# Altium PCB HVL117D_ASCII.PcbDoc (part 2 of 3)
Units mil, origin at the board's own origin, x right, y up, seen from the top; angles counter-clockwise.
Board outline 2004.03 x 2004.03 mil, 6 copper layers (Top Layer, InternalPlane1, MidLayer1, InternalPlane2, MidLayer2, Bottom Layer), stack 60.56 mil thick; 218 components, 157 nets, 658 pads, 273 vias.
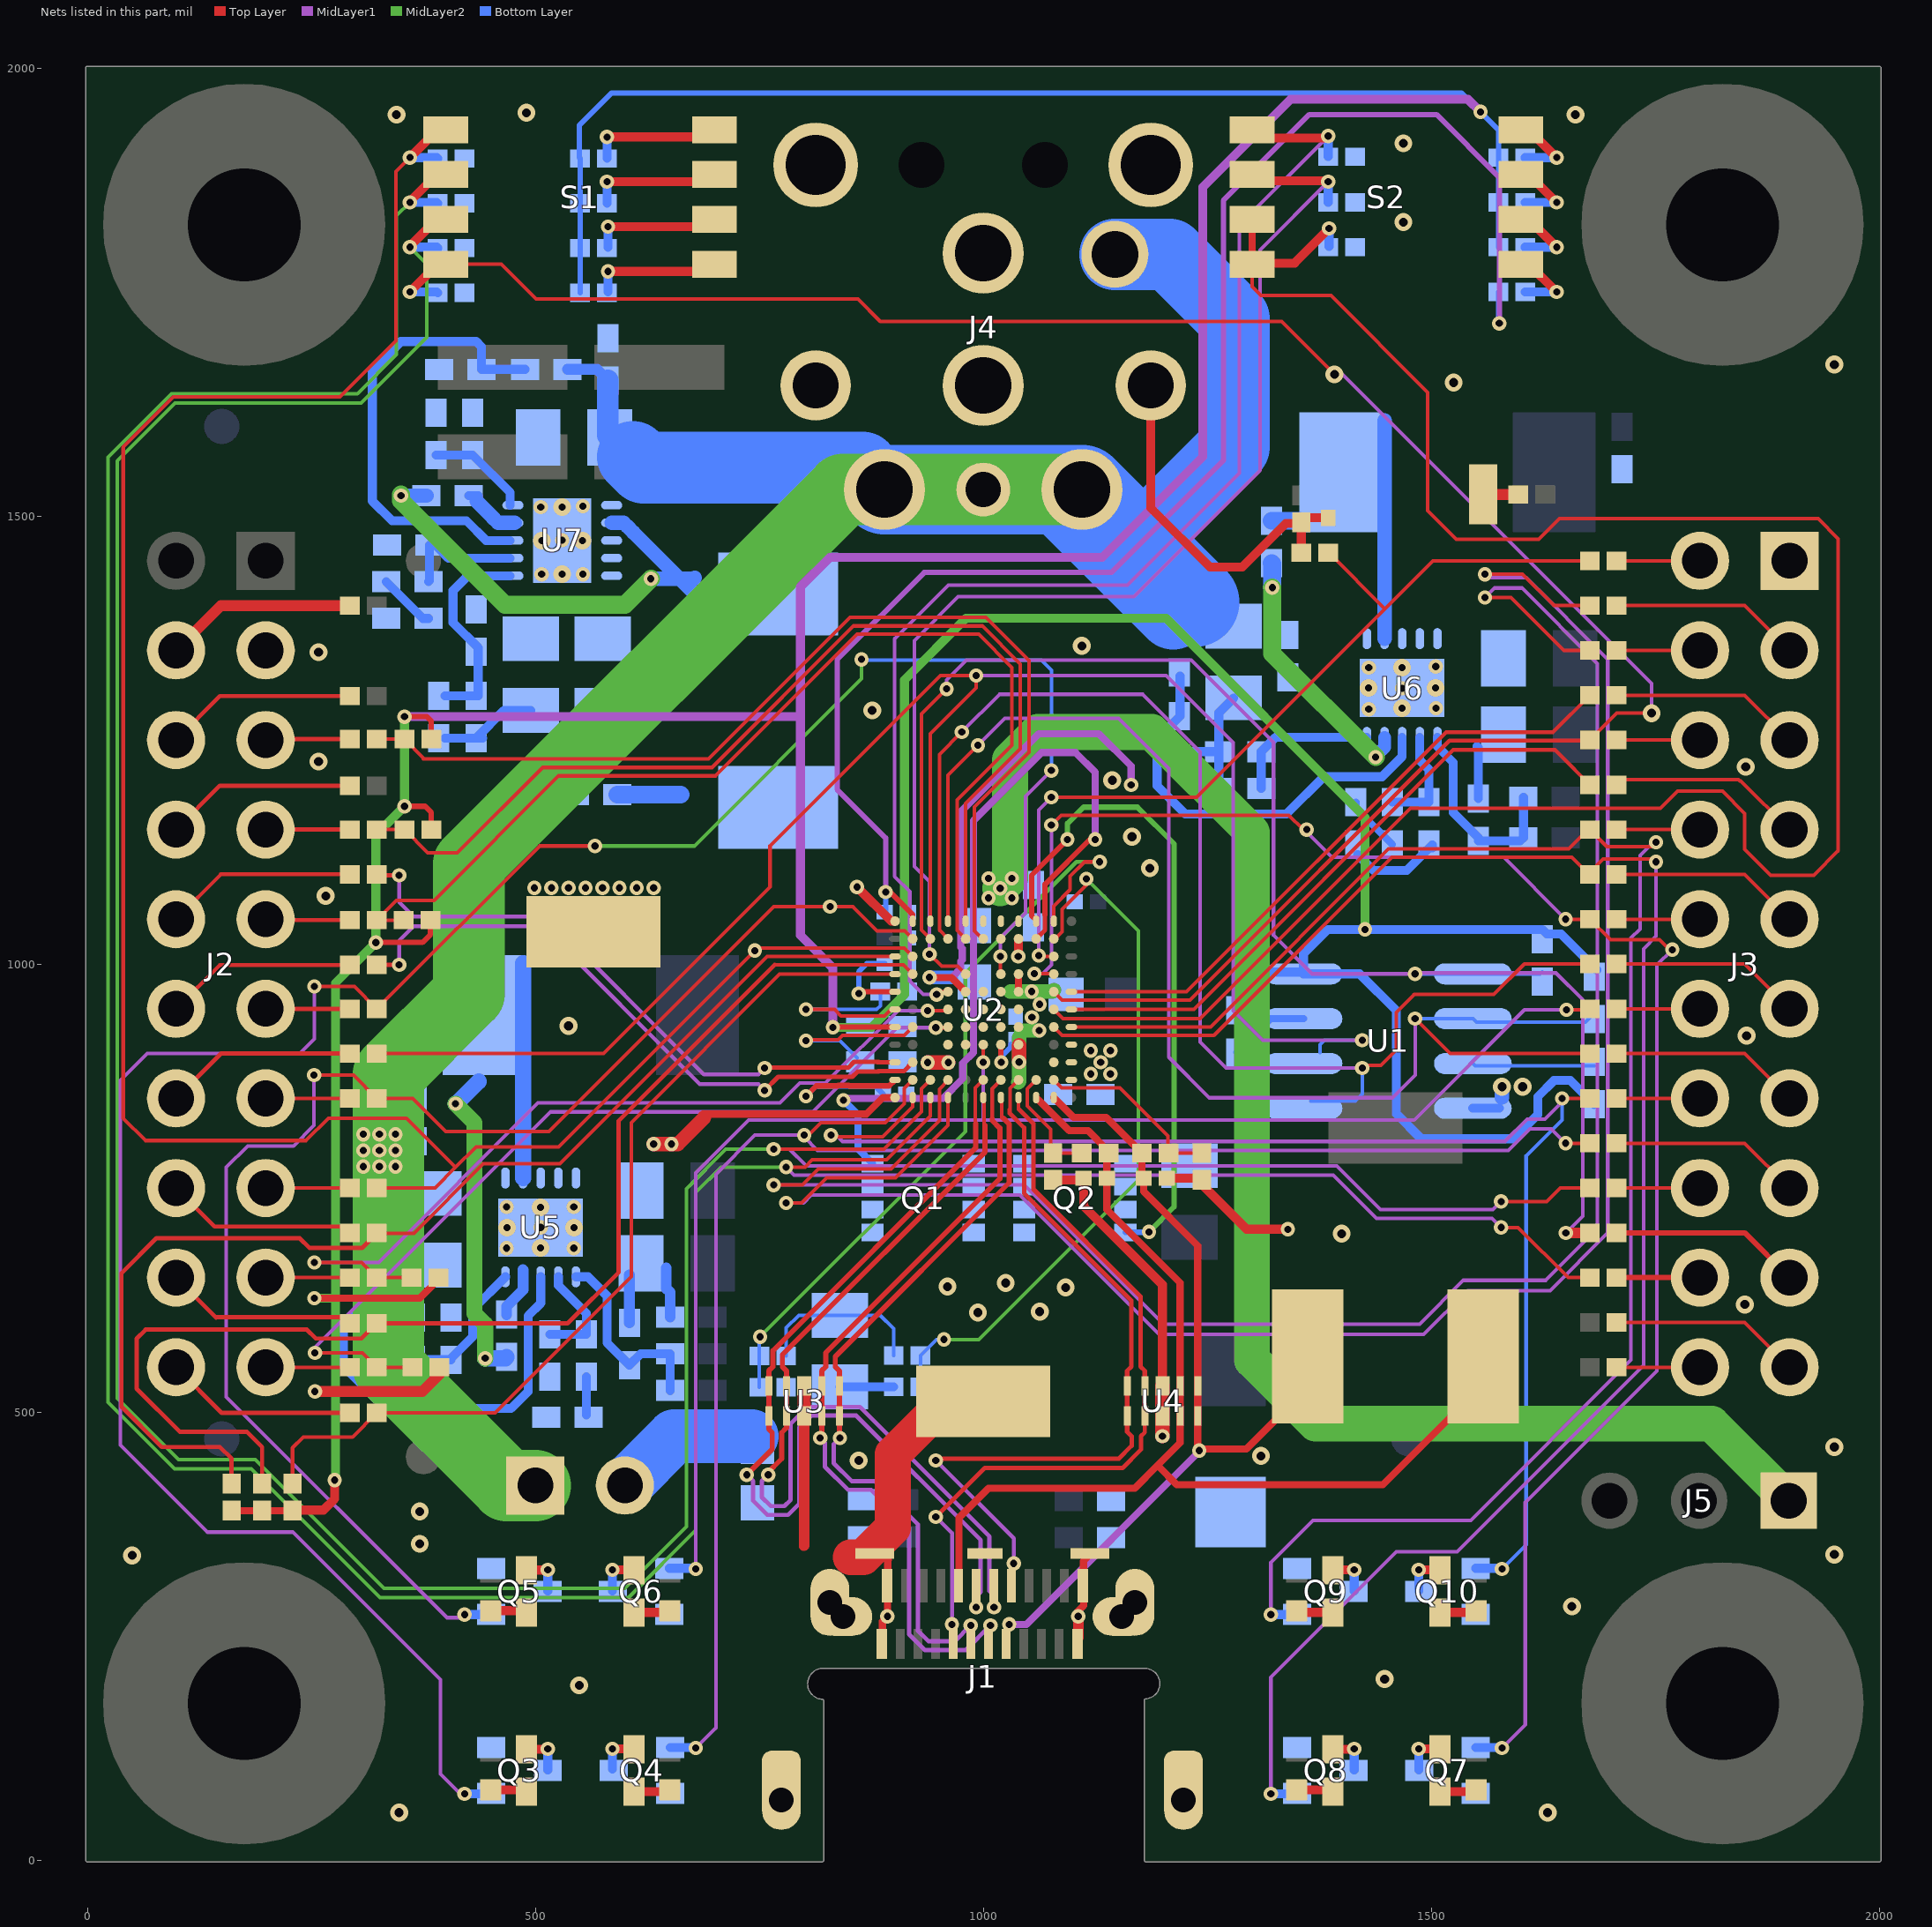
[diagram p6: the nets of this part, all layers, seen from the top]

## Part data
C1 C4: "CAP, CERM, 10 µF, 25 V, +/- 20%, X5R, 0603"
C2 C12: "CAP, CERM, 0.1 µF, 10 V, +/- 10%, X5R, 0201"
C3: "CAP, CERM, 0.22 µF, 6.3 V, +/- 20%, X5R, 0201"
C5: "CAP, CERM, 0.1 µF, 50 V, +/- 20%, C0G/NP0, 0402"
C6: "CAP, CERM, 1 µF, 35 V, +/- 10%, JB, 0402"
C7 C8 C9 C10: "CAP, CERM, 0.01 µF, 50 V, +/- 10%, X7R, 0402"
C11: "CAP, CERM, 22 µF, 10 V, +/- 20%, X5R, 0603"
C13 C16 C17 C18: "CAP, CERM, 1 µF, 10 V, +/- 20%, X5R, 0201"
C14: "CAP, CERM, 10 µF, 10 V, +/- 20%, X5R, 0402"
C15 C19: "CAP, CERM, 220 pF, 25 V, +/- 10%, X7R, 0201"
C20 C23 C26 C31 C34 C37 C42 C45 C48: "CAP, CERM, 0.1uF, 50V, +/-20%, C0G/NP0, 0402"
C22 C33 C44: "CAP, CERM, 10 µF, 25 V, +/- 10%, X5R, 0805"
C24 C25 C35 C36 C46 C47: "CAP, CERM, 22 µF, 35 V, +/- 20%, X5R, 0805"
C27 C30 C38 C41 C49 C52: "CAP, CERM, 120 pF, 50 V, +/- 5%, C0G/NP0, 0402"
C28: "CAP, CERM, 330 pF, 50 V, +/- 5%, C0G/NP0, 0402"
C29: "CAP, CERM, 5600 pF, 50 V, +/- 10%, X7R, 0402"
C39: "CAP, CERM, 100 pF, 50 V, +/- 10%, X7R, 0402"
C40: "CAP, CERM, 2200 pF, 50 V, +/- 10%, X5R, 0402"
C50: "CAP, CERM, 91 pF, 50 V, +/- 5%, C0G/NP0, 0402"
C51: "CAP, CERM, 1800 pF, 50 V, +/- 10%, X7R, 0402"
C53: "CAP, CERM, 0.01 µF, 10 V, +/- 10%, X5R, 0201"
D1: "Diode, Schottky, 40 V, 3 A, SMA"
D2 D3 D4 D5 D6 D7 D8 D9: "LED, White, SMD"
FID1 FID2 FID3 FID4 FID5 FID6: "Fiducial mark.  There is nothing to buy or mount."
H1 H2 H3 H4: "Machine Screw, Round, #4-40 x 1/4, Nylon, Philips panhead"
H5 H6 H7 H8: "Standoff, Hex, 0.5\"L #4-40 Nylon"
J1: "Connector, Receptacle, USB Type C, R/A, SMT"
J2 J3: "Receptacle, 100mil, 10x2, Gold, TH"
J4: "Connector,  DC Power Jack, R/A, 3 Pos, TH"
J5: "Receptacle, 100mil, 3x1, Gold, TH"
J6: "Header, 100mil, 2x1, Tin, TH"
J7: "Header, 100mil, 2x2, Tin, SMT"
L1: "Ferrite Bead, 21 ohm @ 100MHz, 6A, 0805"
Logo1: library part TI_Logo, "Texas Instrument Corporate Signature"
Logo2: library part Pb-Free
Logo3: library part FCC_disclaimer, "FCC_disclaimer"
Q1 Q2: "MOSFET, N-CH, 30 V, 60 A, SON 3.3x3.3mm"
Q3 Q4 Q5 Q6 Q7 Q8 Q9 Q10: library part "DTC114EUAT106, Rohm", "Transistor, NPN, 50 V, 0.05 A, SOT-323"
R1: "RES, 0.01 ohm, 1%, 0.25W, 0805"
R2 R3 R5 R6 R10 R11 R16 R17 R18 R19 R22 R23 R30 R31 R32 R34 R35 R36 R37 R38 R39 R40 R41 R46 R47 R48 R50 R51 R53 R54 R56 R57 R58 R59 R60 R61 R62 R63 R64 R65 R66 R67 R68 R69 R71: "RES, 0, 5%, 0.05 W, 0201"
R4 R7 R8 R9: "RES, 3.3 k, 5%, 0.063 W, 0402"
R12 R13 R14 R15 R27 R42 R43 R44 R45: "RES, 1.00 k, 1%, 0.05 W, 0201"
R20 R75 R76 R79 R80: "RES, 3.83 k, 1%, 0.05 W, 0201"
R21 R24 R25 R26 R29 R33 R49 R52 R55 R70: "RES, 100 k, 1%, 0.05 W, 0201"
R28: "RES, 15.0 k, 1%, 0.063 W, 0402"
R72 R73 R74 R86 R87 R89 R90 R96: "RES, 560, 5%, 0.063 W, 0402"
R77 R78: "RES, 9.09 k, 1%, 0.05 W, 0201"
R81 R91 R101: "RES, 220 k, 5%, 0.063 W, 0402"
R82 R92 R102: "RES, 100 k, 1%, 0.063 W, 0402"
R83 R93 R103: "RES, 43.2 k, 1%, 0.063 W, 0402"
R84: "RES, 32.4 k, 1%, 0.063 W, 0402"
R85: "RES, 2.74 k, 1%, 0.063 W, 0402"
R88 R97 R109: "RES, 47.5 k, 1%, 0.063 W, 0402"
R94: "RES, 19.1 k, 1%, 0.063 W, 0402"
R95: "RES, 8.45 k, 1%, 0.063 W, 0402"
R104: "RES, 7.15 k, 1%, 0.063 W, 0402"
R108: "RES, 9.53 k, 1%, 0.063 W, 0402"
S1 S2: "DIP Switch, SPST 4Pos, Slide, SMT"
S3: "SWITCH TACTILE SPST-NO 0.05A 12V"
TP1 TP2 TP3 TP4 TP5: library part 5019, "Test Point, Miniature, SMT"
U1: "3V, 8Mbit, Serial Flash Memory with Dual and Qual SPI, SOIC-8"
U2: "TPS65982 Preview Specification, ZQZ0096A"
U3 U4: "1, 4, 6 CHANNEL PROTECTION SOLUTION FOR SUPER-SPEED (UP TO 6 GBPS) INTERFACE, DQA0010A"
U5 U6 U7: "4.5V to 28V Input, 3A Output, Synchronous SWIFT Step-Down DC-DC Converter, DRC0010J"
ZZ2 ZZ3 ZZ4: library part AssemblyNote

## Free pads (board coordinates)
  round 75 hole 52: 0(1147,1792)

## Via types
v1: diameter 16, hole 8, Top Layer to Bottom Layer, tented both sides, 166 vias
v2: diameter 16, hole 8.1, Top Layer to Bottom Layer, tented both sides, 54 vias
v3: diameter 20, hole 10, Top Layer to Bottom Layer, tented both sides, 41 vias
v4: diameter 19.68, hole 7.87, Top Layer to Bottom Layer, 12 vias

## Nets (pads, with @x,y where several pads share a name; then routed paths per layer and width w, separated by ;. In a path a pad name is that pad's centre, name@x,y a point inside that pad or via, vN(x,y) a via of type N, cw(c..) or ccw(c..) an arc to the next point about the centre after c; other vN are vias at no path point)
3V3_VSENSE: C27.2 R82.1 R84.2 U5.6 | length 222.7
  Bottom Layer w10: U5.6@545.37,650.88 558.88,650.88 580,629.76 580,577.38 R84.2@605,552.38 617.62,565 647.38,565 R82.1@650.38,565 C27.2@650.38,524
5V_VSENSE: C38.2 R92.1 R94.2 U6.6 | length 231.3
  Bottom Layer w10: U6.6@1506.97,1252.88 1506.97,1242.63 1524.6,1225 1524.6,1169 1552.6,1141 R94.2@1552.6,1137.38 1599.35,1137.38 C38.2@1602.98,1141 R92.1@1602.98,1186
12V_VSENSE: C49.2 R102.1 R104.2 U7.6 | length 236.7
  Bottom Layer w10: C49.2@399.12,1299.31 436.12,1299.31 436.12,1353.06 408.12,1381.06 408.12,1416.69 424.75,1433.32 U7.6@472,1433.32
AUX_N: R34.2 U2.J2 | length 720.6
  Top Layer w5: R34.2@322.96,999 v1(348,999) ; v1(756,859) 771,874 853.85,874 859.66,879.82 883,879.82 ; 883,880.32 911.26,880.32 U2.J2@921.26,890.32
  MidLayer1 w4.4: v1(348,999) 348,1026.1 364,1042.1 507.44,1042.1 683.49,866.05 748.95,866.05 v1(756,859)
AUX_P: R31.2 U2.J1 | length 693.9
  Top Layer w5: R31.2@323.96,1099 v1(348,1099) ; v1(756,884) 756.5,884.5 849.5,884.5 855.82,890.82 883,890.82 ; 882,890.32 U2.J1@901.57,890.32
  MidLayer1 w4.4: v1(348,1099) 348,1069 364,1053 511.95,1053 688,876.95 748.95,876.95 v1(756,884)
BUSPOWERZ: R49.1 S2.3 S2.4 U2.F10 | length 2459.4
  Top Layer w4: U2.F10@1078.74,949.37 1088.94,939.17 1242.17,939.17 1477,1174 1756,1174 1775,1193 1825,1193 1850,1168 1850,1128 1879,1099 1927,1099 1954.33,1126.33 1954.33,1474.67 1932,1497 1643,1497 1620,1474 1528,1474 1496,1506 1496,1638 1388,1746 1310,1746 1300,1756 S2.4@1300,1781
  Top Layer w8: S2.4@1300,1781 S2.3@1300,1831
  Top Layer w10: S2.4@1313,1782 1347,1782 ; 1348,1782 1347,1782 ; v1(1386,1821) 1347,1782
  Bottom Layer w10: R49.1@1386,1800.96 v1(1386,1821)
C_CC1: C15.1 J1.A5 R10.2 TP1.1 U2.L9 U4.2 U4.9 | length 1273.6
  Top Layer w8: J1.A5@973.11,305.31 973,305.42 973,382 1006,415 1169.1,415 1194.55,440.45 ; U2.L9@1061,849 1096,814 1117,814 1138,793 C15.1@1138,761 1138,726 1219.69,644.31 U4.2@1219.69,529.1 U4.9@1219.69,495.64 1219.69,465.58 1194.55,440.45 ; TP1.1@1550.5,569.5 1550.5,523.5 1446,419 1216,419 1194.55,440.45
C_CC2: C19.1 J1.B5 R11.2 TP2.1 U2.L10 U4.1 U4.10 | length 964.3
  Top Layer w8: U2.L10@1078.74,850.94 1100.89,828.8 1137.24,828.8 R11.2@1177.04,789 1177.04,762.97 C19.1@1179.01,761 1179.01,745.99 1239.37,685.63 U4.1@1239.37,529.1 U4.10@1239.37,495.64 v1@1239.37,458.63 ; v1(1241,457) v1@1239.37,458.63 ; 1302.96,468 1293.59,458.63 v1@1239.37,458.63 ; 1303,468 1377,542 TP2.1@1377,562
  MidLayer1 w8: v1(1029,263) 1048,263 v1@1239.37,454.37
C_SBU_N: J1.B8 U2.L8 U4.4 U4.7 | length 840.3
  Top Layer w4: 1039.37,837.63 U2.L8@1039.37,850.94
  Top Layer w4.8: v1(947,383) 1001.6,437.6 1155.6,437.6 1176,458 1176,473 1180.32,477.32 U4.7@1180.32,495.64
  Top Layer w5: 1040.08,837.63 1056,821.71 1056,748.5 1175.72,628.78 1175.72,550.59 1180.32,546 U4.4@1180.32,529.1 U4.7@1180.32,495.64
  MidLayer1 w4.4: v1(947,383) 965,365 v1(965,263)
C_SBU_P: J1.A8 U2.K8 U4.5 U4.6 | length 892.4
  Top Layer w4: 1030,837 1030,861.26 U2.K8@1039.37,870.63
  Top Layer w4.4: J1.A8@1032.17,305.31 1032.3,305.44 1034,307.15 v1(1034,331)
  Top Layer w5: v1(947,446) 949,448 1151.29,448 1165.6,462.31 1165.6,473 1160.63,477.97 U4.6@1160.63,495.64 U4.5@1160.63,529.1 1160.63,546 1165.22,550.59 1165.22,624.43 1045.5,744.15 1045.5,817.36 1029.37,833.49 1029.37,837.63 ; J1.A8@1032.17,305.31 1032.17,306.26 J1.A8@1032.17,321.83
  MidLayer1 w4.4: v1(947,446) 1034,359 v1(1034,331)
C_USB_B_N: J1.B7 U2.L7 U3.1 U3.10 | length 806.4
  Top Layer w4: 1020.68,828.32 U2.L7@1020.68,848.94
  Top Layer w5.8: v1(840,471) 839.37,471.63 U3.10@839.37,495.64 U3.1@839.37,529.1 839.37,546 834.8,550.57 834.8,561.8 1029,756 1029,821.27 1022.27,828
  MidLayer1 w4.8: v1(840,471) 833,464 833,443 853,423 878.86,423 927,374.86 927,256 939,244 968,244 v1(986,262)
C_USB_B_P: J1.B6 U2.K7 U3.2 U3.9 | length 875.1
  Top Layer w4: 1010,828 1010,860.94 U2.K7@1019.68,870.63
  Top Layer w5.8: v1(818,471) 819.69,472.69 U3.9@819.69,495.64 U3.2@819.69,529.1 819.69,546 824.25,550.57 824.25,566.17 1018.45,760.37 1018.45,816.9 1010,825.35 1010,828
  MidLayer1 w4.8: v1(818,471) 823.2,465.8 823.2,438.94 848.94,413.2 874.8,413.2 917.2,370.8 917.2,251.94 934.94,234.2 980.2,234.2 v1(1008,262)
C_USB_T_N: J1.A7 U2.L6 U3.4 U3.7 | length 1057.1
  Top Layer w4: 1001,820 U2.L6@1001,848.94
  Top Layer w5.8: v1@756,429 758.5,431.5 775,448 775,477 780.32,482.32 U3.7@780.32,495.64 U3.4@780.32,529.1 780.32,546 775.75,550.57 775.75,564 1002,790.25 1002,820
  MidLayer1 w4.8: v1(760,430) 752.9,422.9 752.9,405 762.9,395 778,395 785,402 785,486.86 803.94,505.8 862.2,505.8 1006.9,361.1 1006.9,300.1 1012,295 v1(1012,282) 1011,281 1011,278 1012.75,279.75 v1@1012.75,281.5
C_USB_T_P: J1.A6 U2.K6 U3.5 U3.6 | length 1076.2
  Top Layer w4: 991,822 991,861.63 U2.K6@1000,870.63
  Top Layer w5.8: v1(736,430) 764.45,458.45 764.45,477 760.63,480.82 U3.6@760.63,495.64 U3.5@760.63,529.1 760.63,546 765.2,550.57 765.2,568.37 991.45,794.62 991.45,822
  MidLayer1 w4.8: v1(736,430) 743.1,422.9 743.1,400.94 758.84,385.2 782.06,385.2 794.8,397.94 794.8,482.8 808,496 858.14,496 997.1,357.04 997.1,299.1 992,294 v1(992,282)
DEBUG_1: Q10.1 R61.1 U2.L2 | length 1570.6
  Top Layer w4: v1@829,813.37 835.37,807 887.63,807 921.26,840.63 U2.L2@921.26,850.94 ; v1@1650,850 R61.1@1677.04,850
  MidLayer1 w4: v1(830,809) 836,809 843,802 1582,802 1607,827 1627,827 v1@1650,850
  Bottom Layer w4: v1(1579,325) 1606,352 1606,786 1646,826 v1(1646,850)
  Bottom Layer w10: Q10.1@1549.5,325.59 v1@1578.41,325.59
DEBUG_2: Q4.1 R64.1 U2.K2 | length 1847.9
  Top Layer w4: v1@805,809 819,823 890.63,823 911.91,844.28 911.91,846.55 912,846.63 912,855.26 911.91,855.34 911.91,861.28 U2.K2@921.26,870.63 ; v1(1650,800) R64.1@1677.04,800
  MidLayer1 w4: v1(679,125) 701.5,147.5 701.5,765.5 745,809 v1(800,809) 800,807 815,792 1586.14,792 1610.14,816 1634,816 v1(1650,800)
  Bottom Layer w10: Q4.1@650.5,125.59 v1@678.41,125.59
DEBUG_3: R29.1 R65.1 S1.2 U2.L3 | length 4097
  Top Layer w4: v1(780,773.37) 801,773.37 809,781.37 892,781.37 940.94,830.32 U2.L3@940.94,850.94 ; v1(1578,706) 1597,706 1653,650 R65.1@1677.04,650
  Top Layer w10: v1(360,1850) 359,1850 S1.2@390,1881
  MidLayer1 w4: v1(780,773.37) 788.87,764.5 1390.5,764.5 1439,716 1568,716 v1(1578,706)
  MidLayer2 w4: v1(360,1850) 345,1835 345,1680 301.37,1636.37 93.7,1636.37 23,1565.67 23,511 97.37,436.63 183.01,436.63 326.64,293 604,293 679,368 679,745 707.37,773.37 v1(780,773.37)
  Bottom Layer w10: v1(360,1850) 390.04,1850 R29.1@391.04,1849
DEBUG_4: R25.1 R63.1 S1.3 U2.K3 | length 4045.7
  Top Layer w4: v1(766,793.37) 889,793.37 931,835.37 931,860.68 U2.K3@940.94,870.63 ; v1(1578,735) 1629,735 1644,750 R63.1@1677.04,750
  Top Layer w10: v1(360,1800) 359,1800 S1.3@388,1829
  MidLayer1 w4: v1(766,793.37) 783.63,793.37 802.5,774.5 1394.64,774.5 1443.14,726 1569,726 v1(1578,735)
  MidLayer2 w4: v1(360,1800) 379,1781 379,1699.33 305.67,1626 98,1626 33.37,1561.37 33.37,515.3 101.67,447 187.3,447 330.93,303.37 599.7,303.37 668.63,372.3 668.63,749.3 712.7,793.37 v1(766,793.37)
  Bottom Layer w10: v1(360,1800) 390.04,1800 R25.1@391.04,1799
DEBUG_CTL1: R55.1 S2.1 U2.E4 | length 1422
  Top Layer w4: v1@948,965 952.06,969.06 U2.E4@960.63,969.06
  Top Layer w10: S2.1@1306,1922 1383,1922 v1(1385,1924)
  MidLayer1 w4: v1@949,966 v1(948,966) 933,966 918,981 918,1080.75 901,1097.75 901,1363 961,1423 1161,1423 1286,1548 1286,1825 v1(1385,1924)
  Bottom Layer w10: v1(1385,1924) R55.1@1385.04,1901 R55.1@1385.04,1901
DEBUG_CTL2: R52.1 S2.2 U2.D5 | length 1334.2
  Top Layer w4: v1(940,1011) 953.5,997.5 971.56,997.5 U2.D5@980.32,988.74
  Top Layer w10: S2.2@1304,1874 1386,1874 v1(1385,1873)
  MidLayer1 w4: v1@940,1008 v1(940,1011) 940,1092 923,1109 923,1361 972,1410 1168,1410 1309,1551 1309,1797 v1(1385,1873)
  Bottom Layer w10: v1(1385,1873) R52.1@1385.04,1850 R52.1@1385.04,1850
"EXTERNAL POWER": C22.1 C23.1 C33.1 C34.1 C44.1 C45.1 J4.1 J4.2 J4.3 J6.1 pad.0 R81.2 R91.2 R101.2 U5.1 U6.1 U7.1 | length 3136.3
  MidLayer2 w80: J6.1@500,418 468,418 336,550 336,877 425.9,966.9 425.9,1111.9 843.53,1529.53 J4.3@889.76,1529.53 J4.1@1000,1529.53 J4.2@1110.24,1529.53
  Bottom Layer w12: R101.2@535.74,1663.69 568.69,1663.69 C45.1@581,1651.38
  Bottom Layer w24: C44.1@581,1589.8 C45.1@581,1651.38
  Bottom Layer w80: 609,1566 621,1554 865.29,1554 J4.3@889.76,1529.53 ; J4.2@1073.47,1529.53 1212,1391 ; pad.0@1147,1792 1208,1792 1280,1720 1280,1577 1171.38,1468.38
  Bottom Layer w100: J4.3@889.76,1529.53 J4.1@1000,1529.53 1073.47,1529.53 J4.2@1110.24,1529.53 1171.38,1468.38 1235.76,1404
  other v1: 308,774 326,774 344,774 308,792 326,792 344,792 308,810 326,810 344,810
GND: C1.2 C2.2 C3.2 C4.2 C5.2 C6.2 C7.2 C8.2 C9.2 C10.2 C11.2 C12.2 C13.2 C14.2 C15.2 C16.2 C17.2 C18.2 C19.2 C22.2 C23.2 C24.2 C25.2 C26.2 C28.2 C29.2 C30.2 C33.2 C34.2 C35.2 C36.2 C37.2 C39.2 C40.2 C41.2 C44.2 C45.2 C46.2 C47.2 C48.2 C50.2 C51.2 C52.2 C53.2 D1.2 J1.1 J1.2 J1.3 J1.A1 J1.A12 J1.B1 J1.B12 J1.H1 J1.H2 J1.H3 J1.H4 J1.H5 J1.H6 J1.H7 J1.H8 J2.3 J3.1 J4.4 J4.5 J4.6 J4.7 J4.8 J4.9 Q3.2 Q4.2 Q5.2 Q6.2 Q7.2 Q8.2 Q9.2 Q10.2 R21.2 R22.2 R24.2 R25.2 R26.1 R28.1 R29.2 R30.2 R33.2 R49.2 R52.2 R55.2 R56.1 R70.1 R83.1 R84.1 R88.1 R93.1 R94.1 R97.1 R103.1 R104.1 R109.1 TP4.1 TP5.1 U1.4 U2.A1 U2.B8 U2.D8 U2.E5 U2.E6 U2.E7 U2.E8 U2.F5 U2.F6 U2.F7 U2.F8 U2.G5 U2.G6 U2.G7 U2.G8 U2.H4 U2.H5 U2.H8 U2.L1 U3.3 U3.8 U4.3 U4.8 U5.3 U5.4 U5.5 U5.11 U6.3 U6.4 U6.5 U6.11 U7.3 U7.4 U7.5 U7.11 | length 3329
  Top Layer w6: R22.2@1077.02,760.47 R22.2@1077.02,761 ; C15.2@1110.06,759.04 C15.2@1112.02,761 ; R30.2@1237.04,761 R30.2@1239,759.04
  Top Layer w8: 687.5,832.5 869.5,832.5 887.94,850.94 U2.L1@901.57,850.94 ; J1.B12@887.48,240.35 887.48,266.48 v1(893,272) 893,304.93 893.39,305.31 893.39,334.39 894,335 ; v2(940,985) 964.37,985 U2.E5@980.32,969.06 ; U2.E8@1039.37,969.06 U2.D8@1039.37,988.74 ; J1.B1@1105.98,240.35 v1(1106,272) 1106,278 1112,284 1112,305.2 1111.89,305.31 1111.89,333.46 J1.1@1119.76,341.34
  Top Layer w10: 799,350 800,351 ; v1(859,1086) 897.2,1047.8 U2.A1@901.57,1047.8 ; v2(1039,1008.37) 1039.37,1008.74 U2.B8@1039.37,1028.11 ; R22.2@1078,759.04 C15.2@1110.06,759.04 ; C15.2@1112.02,761 1112.02,729.98 1200,642 U4.8@1200,495.64 ; J4.6@1187.01,1645.67 1187.01,1508.99 1253,1443 1289,1443 1337.68,1491.68 1353.64,1491.68 R26.1@1355,1493.04 1359.97,1498.01 C53.2@1385,1498.01 ; C19.2@1204.99,761 R30.2@1237.04,761 ; R30.2@1239,759.04 1294.04,704 v1(1340,704) ; R70.1@1355.04,1459 R26.1@1355,1493.04
  Top Layer w12: v1(254,523) 374,523 392.96,541.96 R24.2@392.96,550 ; 800,351 U3.8@800,495.64 ; v1(1106,272) 1106.3,271.7 J1.B1@1106.3,248.3
  Top Layer w15: U3.8@800,495.64 U3.3@800,529.1
  Top Layer w16: v1(632,799) v1(652,799) 659,799 688.5,828.5 ; v2(938,890) v2(961,890) ; v2(1040,890.67) U2.H8@1040,909.37 ; v1(1200,473) U4.8@1200,495.64 U4.3@1200,529.1
  Top Layer w40: 852,338 866,338 899,371 899,453 958,512 TP4.1@1000,512
  MidLayer1 w8: v2(940,985) 965,985 975,995 975,1003.08 976.5,1004.58 976.5,1017.42 975,1018.92 975,1170 1062,1257 1129,1257 1165,1221 v2(1165,1200)
  MidLayer2 w16: 1030,969 1030.37,969.37 v2(1054,969.37) 1077.37,969.37 1079,971 ; 1039,868 1040,869 v2(1040,890.67) 1040,918 ; 1042.33,925.67 v2(1062.3,925.67)
  Bottom Layer w8: C40.2@1416,1180.62 1416,1173.98 C39.2@1456.6,1133.38
  Bottom Layer w10: R93.1@1219.6,1229.38 1227.22,1237 C41.2@1262.98,1237 ; R97.1@1262.98,1196 C41.2@1262.98,1237 ; C33.2@1279.6,1297 1262.98,1280.38 C41.2@1262.98,1237 ; U1.4@1546.49,839 U1.4@1576,839 ; 1551,1243 1552.6,1241.4 R94.1@1552.6,1184.62
  Bottom Layer w12: R84.1@605,599.62 C25.2@605,653 ; 646.1,660.8 646.1,637.96 650.38,633.68 C26.2@650.38,606
  Bottom Layer w15: v2(940,985) 964.37,985
  Bottom Layer w16: 1579,851 v3(1579,863)
  other v2: 468,683 543,683 506,706 468,729 543,729 1054.3,940.57 1062.8,955.07 499,1085 518,1085 537,1085 556,1085 575,1085 594,1085 613,1085 632,1085 1430.2,1284.4 1505.3,1285.5 1467.6,1307.67 1430.2,1330.7 1505,1332.1 507,1435 553,1435 530,1473 506,1510 553,1511
  other v3: 348,53 1630,53 549,195 1448,202 1657,283 50,340 1950,341 371,353 371,389 861,446 1310,451 1950,461 994,611 1063,612 1850,620 1092,639 960,640 1025,644 1400,699 1602,863 1852,920 537,931 266,1076 1186,1107 1166,1142 1144,1205 1851,1220 258,1226 876,1283 258,1348 1110,1355 1525,1649 1950,1669 1469,1828 1469,1916 345,1948 1661,1948 490,1950
  other v4: 506,683.36 468.6,706 543.4,706 506,728.64 1467.6,1285.36 1430.2,1308 1505,1308 1467.6,1330.64 530.12,1435.28 507.48,1472.69 552.76,1472.69 530.12,1510.09
GPIO0: Q5.1 R35.1 U2.B2 | length 1636.4
  Top Layer w4: v1(253,876) 296.96,876 R35.1@322.96,850 363,850 400,813 515,813 766,1064 v1(829,1064) 854.47,1064 881.47,1037 912.37,1037 U2.B2@921.26,1028.11
  MidLayer1 w4: v1(253,876) 253,820 230,797 179,797 155,773 155,517 401.5,270.5 v1@417.5,270.5
  Bottom Layer w10: v1(421,274) Q5.1@450.09,274
GPIO1: R33.1 R37.1 S1.1 U2.C2 | length 2526.5
  Top Layer w4: R37.1@322.96,750 388,750 411,773 ; v1(360,1900) 344.5,1884.5 344.5,1695.5 282,1633 96,1633 40,1577 40,828 65,803 244,803 269,828 356,828 411,773 ; U2.C2@921.26,1008.43 911.68,1018 748,1018 v1(745,1015) 526,796 434,796 411,773
  Top Layer w10: v1(360,1900) S1.1@398,1938
  Bottom Layer w10: v1(360,1900) 390.04,1900 R33.1@391.04,1899
GPIO2: Q7.1 R57.1 U2.D10 | length 1964.3
  Top Layer w4: v1(1057,989.37) 1078.11,989.37 U2.D10@1078.74,988.74 ; v1@1082,1155 v1(1076,1155) 1087,1166 1341,1166 v1@1357,1150 ; v1(1650,1050) R57.1@1677.04,1050 1700.04,1027 1755,1027 1766,1016 v1(1769,1016)
  MidLayer1 w4: v1(1057,989.37) 1066.46,989.37 1076,998.91 v1(1076,1155) ; v1@1358,1150 1389,1119 1581,1119 v1(1650,1050) ; v1(1579,125) 1605,151 1605,398.99 1752,545.99 1752,999 v1(1769,1016)
  Bottom Layer w10: Q7.1@1549.5,125.59 v1@1578.41,125.59
  other v1: 1361,1150
GPIO3: Q9.1 R53.1 U2.G11 | length 1923
  Top Layer w4: U2.G11@1098.43,929.69 1253.69,929.69 1452.35,1128.35 1653.35,1128.35 R53.1@1673,1148 ; R53.1@1677.04,1150 1696.04,1131 1746,1131 v1(1751,1136)
  MidLayer1 w4: v1(1321,274) 1321,332 1368,379 1544,379 1723,558 1723,1029 1733,1039 1733,1121 1748,1136 v1(1751,1136)
  Bottom Layer w10: v1(1321,274) Q9.1@1350.09,274
GPIO4_HPD: R46.2 R70.2 U2.C10 | length 1002.2
  Top Layer w4: v1(1062,1009.37) 1062.94,1008.43 U2.C10@1078.74,1008.43 ; v1(1076,1186) 1238,1186 1448.46,1396.46 ; R70.2@1384.96,1459 1385.91,1459 1448.46,1396.46 ; R46.2@1677.04,1450 1502,1450 1448.46,1396.46
  MidLayer1 w4: v1(1062,1009.37) 1062,1172 v1(1076,1186) v1@1078,1188
GPIO5_HPD: R21.1 R50.2 S1.4 U2.E10 | length 2455
  Top Layer w4: S1.4@400,1781 462,1781 501,1742 860,1742 885,1717 1333,1717 v3(1392,1658) ; U2.E10@1078.74,969.06 1088.09,959.71 1230.71,959.71 1520.34,1249.34 R50.2@1676.38,1249.34 ; R50.2@1674.69,1247.65 R50.2@1676.38,1249.34 ; R50.2@1677.04,1249.34 R50.2@1676.38,1249.34 ; v3(1746,1280) 1707.04,1280 R50.2@1677.04,1250 R50.2@1676.38,1249.34
  Top Layer w10: v1(360,1750) S1.4@391,1781
  MidLayer1 w4: v3(1392,1658) 1401,1658 1746,1313 v3(1746,1280)
  Bottom Layer w10: v1(360,1750) 390.04,1750 R21.1@391.04,1749
GPIO6: Q8.1 R58.1 U2.G10 | length 2056.2
  Top Layer w4: U2.G10@1078.74,929.69 1088.09,920.34 1257.56,920.34 1456.22,1119 1657,1119 R58.1@1673,1103 ; R58.1@1677.04,1100 1677.04,1102.04 1692,1117 v1@1751,1117
  MidLayer1 w4: v1(1321,74) 1321,204 1461,344 1528.8,344 1737,552.2 1737,1017 1751,1031 v1(1751,1114)
  Bottom Layer w10: v1(1321,74) Q8.1@1350.09,74
GPIO7: Q3.1 R36.1 U2.D7 | length 2713.1
  Top Layer w4: v1(253.33,975) 297.96,975 R36.1@322.96,950 504.66,1131.7 v1(566.6,1131.7) ; v1(1019,1008.37) 1019,989.43 U2.D7@1019.68,988.74
  MidLayer1 w4: v1(253.33,975) 253.33,916.33 237,900 67,900 37,870 37,463 134,366 229.26,366 394,201.26 394,96 v1@418.5,71.5 ; v1(1019,1008.37) 1019,1029 1047,1057 1047,1187 v1(1076,1216) v1@1077.5,1217.5
  MidLayer2 w4: v1(566.6,1131.7) 677.4,1131.7 864,1318.3 v1(864,1340)
  Bottom Layer w4: v1(864,1340) 869,1340 870,1339 1065,1339 1076,1328 v1(1076,1216)
  Bottom Layer w10: v1(421,74) Q3.1@450.09,74
GPIO8: Q6.1 R59.1 U2.H6 | length 1628.8
  Top Layer w4: v1(1000,890.37) U2.H6@1000,910 ; v1(1651,949) 1676.04,949 R59.1@1677.04,950
  MidLayer1 w4: v1(679,325) 679,767 738,826 1000,826 ; v1(1000,890.37) 1000,826 ; v1(1651,949) 1604,949 1481,826 1000,826
  Bottom Layer w10: Q6.1@649.5,325.59 v1@678.41,325.59
HV_GATE1: Q1.4 U2.B9 | length 916.9
  Top Layer w5: U2.B9@1059.06,1028.11 1068.94,1038 1068.94,1054.94
  Top Layer w6: 1068.94,1054.94 1068.94,1088.94 1120,1140 v1@1125,1140
  Top Layer w8: U2.B9@1059.06,1028.11 U2.B9@1059.06,1028.11
  MidLayer1 w8: v2(844,848) 844,850 955,850 977,872 977,889.29 989,901.29 989,1160 1065,1236 1103,1236 1125,1214 v1(1125,1139)
  Bottom Layer w8: v2@844,850 v2(844,848) 860,832 860,793.72 Q1.4@876.34,777.39
HV_GATE2: Q2.4 U2.A9 | length 742.4
  Top Layer w6: U2.A9@1059.06,1047.8 1059.06,1048.94 1054,1054 1054,1099 v1(1094,1139)
  MidLayer2 w6: v1(1094,1139) 1094,1157 1112,1175 1172,1175 1213,1134 1213,729 v2(1185,701)
  Bottom Layer w6: Q2.4@1158.66,700.61 1184.61,700.61 v2(1185,701)
HV_SOURCE: C4.1 C5.1 C46.1 C47.1 C48.1 C49.1 J5.1 L4.2 R102.2 U2.A6 U2.A7 U2.A8 U2.B7 | length 1916.3
  MidLayer2 w40: v2(1018.81,1084.59) 1030,1095.78 1030,1228 1061,1259 1188,1259 1300,1147 1300,558 1371,487 1813,487 J5.1@1899,401
  Bottom Layer w10: C49.1@399.12,1252.06 R102.2@441.12,1252.06 ; R102.2@434.12,1252.28 464.83,1283 C47.1@495,1283
  Bottom Layer w20: C48.1@591.62,1189 662,1189
  other v2: 1005.81,1073.59 1031.81,1073.59 1005.81,1095.59 1031.81,1095.59
I2C_IRQ1Z: R40.2 R78.1 U2.C1 | length 1343.7
  Top Layer w4: R40.2@322.96,699.46 364.46,699.46 442,777 527.46,777 758.89,1008.43 U2.C1@901.57,1008.43
  Top Layer w4.8: R78.1@161,419.92 161,448 148,461 83,461 38,506 38,655 77,694 237,694 248,683 306.5,683 322.96,699.46 R40.2@322.96,700
I2C_IRQ2Z: R16.1 R77.1 U2.B6 | length 1162.9
  Top Layer w4: R16.1@322.96,1251 R77.1@354.04,1251 375.04,1230 ; 375.04,1229 693.13,1229 851.13,1387 1002.87,1387 1051,1338.87 1051,1236.13 990,1175.13 990,1037 998.89,1028.11 U2.B6@1000,1028.11
I2C_SCL1: R69.2 R79.1 U2.D2 | length 1414.5
  Top Layer w4: 767,999 911,999 U2.D2@921.26,988.74
  Top Layer w4.8: R79.1@195,419.92 195,461 178,478 103,478 55,526 55,582 65,592 245,592 255,582 305.96,582 R69.2@322.96,599 536,599 593,656 593,825 767,999
I2C_SCL2: R32.1 R75.1 U2.B5 | length 1211.6
  Top Layer w4: R75.1@346,1049 R32.1@322.96,1049 344.96,1071 387,1071 526,1210 701,1210 859,1368 995,1368 1032,1331 1032,1244 971,1183 971,1037.43 U2.B5@980.32,1028.11
I2C_SDA1: R71.2 R80.1 U2.D1 | length 1032.4
  Top Layer w4: R80.1@229,419.92 229,460 241,472 295.96,472 R71.2@322.96,499 455,499 607,651 607,823 772.74,988.74 U2.D1@901.57,988.74
I2C_SDA2: R17.1 R76.1 U2.A5 | length 1164
  Top Layer w4: R17.1@322.96,1150 R76.1@354.04,1150 380.04,1124 413,1124 508.32,1219.32 697.14,1219.32 855.14,1377.32 998.86,1377.32 1041.32,1334.86 1041.32,1240.14 980.32,1179.14 U2.A5@980.32,1047.8
LDO_1V8D: C16.1 R45.2 U2.A2 | length 1732.9
  Top Layer w6: v1(891,1080.37) 896,1080.37 921.26,1055.11 U2.A2@921.26,1047.8 U2.A2@921,1048.06
  MidLayer1 w6: v1(891,1080.37) 891,1140.78 837,1194.78 837,1340 934,1437 1143,1437 1268,1562 1268,1852 1364,1948 1506,1948 1576,1878 v1@1576,1719
  Bottom Layer w6: C16.1@891,1058 v1(891,1080.37) ; R45.2@1575.04,1750 1575.04,1719.96 v1@1576,1719
  other v1: 1576,1715
LDO_3V3: C2.1 C14.1 R4.1 R7.1 R8.1 R9.2 R12.2 R13.2 R14.2 R15.2 R20.2 R42.2 R43.2 R44.2 R75.2 R76.2 R77.2 R78.2 R79.2 R80.2 U1.8 U2.G1 | length 7191.5
  Top Layer w6: v1(322,1024) 374,1024 382.96,1032.96 R75.2@382.96,1049 ; v1(354,1176) 377,1176 383.96,1169.04 R76.2@383.96,1150 ; v1(354,1276) 379,1276 383.96,1271.04 R77.2@383.96,1251 ; v1@831.37,930 v1(832,929.37) ; v1@832.32,929.69 U2.G1@901.57,929.69
  Top Layer w8: R78.2@161,390 R79.2@195,390 R80.2@229,390 ; v1(253.33,627) 371,627 391.96,647.96 R20.2@391.96,650
  Top Layer w10: R80.2@229,390 R80.2@229,390 229.6,390.6 263.6,390.6 276,403 v1(276,424) ; v1(832,929.37) v1@832.32,929.69
  MidLayer1 w10: v1(354,1276) 796,1276 ; v1(832,929.37) 832,996 796,1032 796,1276 ; v1(1555,1951) 1541,1965 1343,1965 1245,1867 1245,1566 1132.75,1453.75 828.75,1453.75 796,1421 796,1276
  MidLayer2 w10: v1(253.33,627) 277,627 ; v1@277,424 277,627 ; v1(354,1276) v1(354,1176) 322,1144 v1(322,1024) 277,979 277,627 ; v1(832,929.37) 875.37,929.37 912,966 912,1317 981,1386 1204,1386 1426,1164 v1(1426,1038.62)
  Bottom Layer w6: R15.2@550.04,1749 R14.2@550.04,1799 R13.2@550.04,1849 R12.2@550.04,1899 549,1900.04 549,1936 585,1972 1534,1972 v1(1555,1951) 1576,1930 ; v1(832,929.37) 861.38,929.37 C14.1@862.38,930.37 ; R44.2@1575.04,1800 R43.2@1575.04,1850 R42.2@1575.04,1900 1575.04,1929.04
  Bottom Layer w8: R8.1@1283,948.62 1287,952.62 C2.1@1287,991.01
  Bottom Layer w10: C2.1@1287,991.01 U1.8@1355.51,991 ; R9.2@1682,843.38 1655.38,870 1637,870 1619,852 1619,832 1592,805 1489,805 1461,833 1461,948 1420,989 U1.8@1357.51,989 1357.51,1011.51 1384.62,1038.62 v1(1426,1038.62) 1624,1038.62 1629.12,1033.5 1645,1033.5 R7.1@1685,993.5
LSX_P2R: R48.2 U2.L4 | length 2225.6
  Top Layer w4: v1(780,733.37) 797,733.37 825,761.37 902,761.37 960.63,820 U2.L4@960.63,850.94 ; v1(1560,1435) 1602,1435 1637,1400 R48.2@1677.04,1400
  MidLayer1 w4: v1(780,733.37) 799.37,733.37 808,742 1040.92,742 1196.29,586.63 1491.71,586.63 1540.71,635.63 1632.63,635.63 1697,700 1697,1340.08 1606.08,1431 v1@1560,1431
LSX_R2P: R47.2 U2.K4 | length 2228.7
  Top Layer w4: v1(766,753.37) 798,753.37 816,771.37 897,771.37 951,825.37 951,860.37 U2.K4@960.63,870 ; v1(1560,1409) 1589,1409 1648,1350 R47.2@1677.04,1350
  MidLayer1 w4: v1(766,753.37) 1045.63,753.37 1201,598 1487,598 1536,647 1627.92,647 1685.63,704.71 1685.63,1335.37 1601.37,1419.63 1570.63,1419.63 v1(1560,1409)
MRESET: R51.1 U2.E11 | length 715.7
  Top Layer w4: U2.E11@1098.43,969.06 1226.84,969.06 1516.47,1258.68 1635.72,1258.68 R51.1@1677.04,1300
NetC1_1: C1.1 J6.2 R1.1 R2.2 R5.2 | length 224.3
  Bottom Layer w10: R1.1@840,528 R5.2@900.04,528
  Bottom Layer w60: J6.2@600,418 655,473 C1.1@741.5,473
NetC3_1: C3.1 U2.H7 | length 42.4
  Top Layer w6: U2.H7@1019.68,910 1019.68,890.69 v1(1020,890.37)
  Bottom Layer w6: v1@1016.7,893.67 1031,907.97 C3.1@1031,910.38
NetC6_1: C6.1 L1.1 Q2.1 Q2.2 Q2.3 U2.H11 U2.J10 U2.J11 U2.K11
  other v2: 1120,877.37 1142,877.37 1131,890.37 1120,903.37 1142,903.37
NetC17_1: C17.1 U2.K1 | length 202.1
  Top Layer w6: v1(802,852.37) 813.63,864 837.49,864 837.99,864.5 850.01,864.5 850.51,864 894.94,864 U2.K1@901.57,870.63
  Bottom Layer w6: v1(802,852.37) 813.63,864 879.01,864 C17.1@888.01,855
NetC18_1: C18.1 U2.E1 | length 100.2
  Top Layer w6: v1(861,967) 861,969.37 861.32,969.06 U2.E1@901.57,969.06
  Bottom Layer w6: v1(861,967) 861,991.37 870,1000.37 C18.1@890.01,1000.37
NetC20_1: C20.1 U5.9 | length 58.1
  Bottom Layer w12: C20.1@468,608.62 468,618 486.31,636.31 U5.9@486.31,650.88 486.31,658.69 U5.9@486,659
NetC20_2: C20.2 L2.1 U5.2 | length 598.3
  MidLayer2 w18: v1(411,844) 432,823 432,610 444,598 v1(444,560)
  Bottom Layer w18: v1(411,844) 412,844 437,869 ; v1(444,560) 466.62,560 C20.2@468,561.38 ; U5.2@486.31,761.12 L2.1@486.31,1000.81
NetC28_1: C28.1 R85.2 U5.7 | length 118.2
  Bottom Layer w10: C28.1@516,586.62 R85.2@557,586.62 557,610 525.68,641.32 U5.7@525.68,650.88
NetC29_1: C29.1 R85.1 | length 42.8
  Bottom Layer w10: C29.1@557,496.62 R85.1@557,539.38
NetC30_1: C30.1 R88.2 U5.10 | length 158.8
  Bottom Layer w10: R88.2@365,558.38 C30.1@406,558.38 ; C30.1@406,558.76 405.38,559.38 430,584 430,614.25 U5.10@466.63,650.88
NetC31_1: C31.1 U6.9 | length 289.6
  MidLayer2 w20: v1(1322.6,1420.1) 1322.6,1346.4 v1(1438,1231)
  Bottom Layer w10: v1@1440,1231 v1@1440,1234
  Bottom Layer w14: v1@1440,1234 1447.91,1241.91 U6.9@1447.91,1252.88
  Bottom Layer w20: C31.1@1322,1447.38 1322.6,1446.78 v1(1322.6,1420.1)
NetC31_2: C31.2 L3.1 U6.2 | length 274.3
  Bottom Layer w16: U6.2@1447.91,1363.12 1447.91,1606.71
  Bottom Layer w20: C31.2@1322,1494.62 L3.1@1352.68,1494.62
NetC39_1: C39.1 R95.2 U6.7 | length 117.5
  Bottom Layer w10: C39.1@1456.6,1180.62 R95.2@1497.6,1180.62 1497.6,1217 1487.28,1227.32 U6.7@1487.28,1252.88
NetC40_1: C40.1 R95.1 | length 105.6
  Bottom Layer w10: C40.1@1418,1122 1435.64,1104.36 1472.6,1104.36 1501.22,1132.98 R95.1@1501.22,1129.76
NetC41_1: C41.1 R97.2 U6.10 | length 165.6
  Bottom Layer w10: R97.2@1310.22,1196 C41.1@1310.22,1237 1326.1,1252.88 U6.10@1428.23,1252.88
NetC42_1: C42.1 U7.9 | length 63
  Bottom Layer w10: C42.1@425.74,1522.69 C42.1@436.12,1522.69
  Bottom Layer w16: C42.1@434.55,1516.6 451.69,1499.11 458.43,1492.37 U7.9@475,1492.37 U7.9@477,1492.37
NetC42_2: C42.2 L4.1 U7.2 | length 606.4
  MidLayer2 w20: v1@350,1524 350,1517 466,1401 600,1401 v1(629,1430)
  Bottom Layer w16: v1(350.12,1522.69) C42.2@378.5,1522.69 ; U7.2@585.24,1492.37 598.63,1492.37 602.5,1488.5 602.76,1488.5 609.5,1481.76 609.5,1481.5 661,1430 ; v1(629,1430) 661,1430 ; 678,1431 677,1430 661,1430 ; L4.1@718.13,1411.13 699,1392 661,1430
NetC50_1: C50.1 R108.2 U7.7 | length 127.1
  Bottom Layer w10: R108.2@380.74,1426.69 381.74,1427.68 C50.1@381.74,1467.69 ; C50.1@391.12,1464.69 402.8,1453 U7.7@472,1453
NetC51_1: C51.1 R108.1 | length 64.2
  Bottom Layer w10: R108.1@333.5,1426.69 374.5,1385.69 C51.1@380.74,1385.69
NetC52_1: C52.1 R109.2 U7.10 | length 114.4
  Bottom Layer w10: C52.1@389.12,1568.06 R109.2@430.12,1568.06 472,1526.18 U7.10@472,1512.06
NetD2_2: D2.2 R72.2 | length 38
  Top Layer w10: D2.2@450,78.35 R72.2@488.03,78.35
NetD3_2: D3.2 R73.2 | length 38
  Top Layer w10: R73.2@610,76.38 D3.2@648.03,76.38
NetD4_2: D4.2 R74.2 | length 38
  Top Layer w10: D4.2@450,278.35 R74.2@488.03,278.35
NetD5_2: D5.2 R86.2 | length 38
  Top Layer w10: R86.2@610,276.38 D5.2@648.03,276.38
NetD6_2: D6.2 R87.2 | length 38
  Top Layer w10: R87.2@1510,76.38 D6.2@1548.03,76.38
NetD7_2: D7.2 R89.2 | length 38
  Top Layer w10: D7.2@1350,78.35 R89.2@1388.03,78.35
NetD8_2: D8.2 R90.2 | length 38
  Top Layer w10: D8.2@1351.97,276.38 R90.2@1390,276.38
NetD9_2: D9.2 R96.2 | length 38
  Top Layer w10: R96.2@1510,276.38 D9.2@1548.03,276.38
NetJ2_4: J2.4 R18.2 | length 214.8
  Top Layer w12: J2.4@99,1350 149,1400 R18.2@293.04,1400
NetJ2_5: J2.5 R16.2 | length 93
  Top Layer w4.8: J2.5@200,1251 R16.2@293.04,1251
NetJ2_6: J2.6 R19.2 | length 214.3
  Top Layer w4.8: J2.6@99,1250 148,1299 R19.2@293.04,1299
NetJ2_7: J2.7 R17.2 | length 94
  Top Layer w4.8: J2.7@199,1150 R17.2@293.04,1150
NetJ2_8: J2.8 R23.1 | length 214.3
  Top Layer w4.8: J2.8@99,1150 148,1199 R23.1@293.04,1199
NetJ2_9: J2.9 R32.2 | length 94.5
  Top Layer w4.8: J2.9@199,1050 200,1049 R32.2@293.04,1049
NetJ2_10: J2.10 R31.1 | length 214.8
  Top Layer w4.4: J2.10@99,1050 149,1100 R31.1@293.04,1100
NetJ2_11: J2.11 R36.2 | length 94
  Top Layer w4.8: J2.11@199,950 R36.2@293.04,950
NetJ2_12: J2.12 R34.1 | length 214.3
  Top Layer w4.4: J2.12@99,950 148,999 R34.1@293.04,999
NetJ2_13: J2.13 R35.2 | length 93
  Top Layer w4: J2.13@200,850 R35.2@293.04,850
NetJ2_14: J2.14 R38.1 | length 214.8
  Top Layer w4.8: J2.14@99,850 149,900 R38.1@293.04,900
NetJ2_15: J2.15 R37.2 | length 93
  Top Layer w4: J2.15@200,750 R37.2@293.04,750
NetJ2_16: J2.16 R40.1 | length 204.9
  Top Layer w4.8: J2.16@99,750 142,707 R40.1@286.04,707
NetJ2_17: J2.17 R39.2 | length 93
  Top Layer w4: J2.17@200,650 R39.2@293.04,650
NetJ2_18: J2.18 R69.1 | length 206
  Top Layer w4.8: J2.18@99,650 143.5,605.5 ; 144,606 R69.1@287.04,606
NetJ2_19: J2.19 R41.2 | length 93
  Top Layer w4: J2.19@200,550 R41.2@293.04,550
NetJ2_20: J2.20 R71.1 | length 215.2
  Top Layer w4.8: J2.20@99,550 150,499 R71.1@293.04,499
NetJ3_2: J3.2 R46.1 | length 93
  Top Layer w4: R46.1@1706.96,1450 J3.2@1800,1450
NetJ3_3: J3.3 R48.1 | length 213.8
  Top Layer w4: R48.1@1706.96,1400 1850,1400 J3.3@1900,1350
NetJ3_4: J3.4 R47.1 | length 93
  Top Layer w4: R47.1@1706.96,1350 J3.4@1800,1350
NetJ3_5: J3.5 R51.2 | length 213.8
  Top Layer w4: R51.2@1706.96,1300 1850,1300 J3.5@1900,1250
NetJ3_6: J3.6 R50.1 | length 93
  Top Layer w4: R50.1@1706.96,1250 J3.6@1800,1250
NetJ3_7: J3.7 R54.2 | length 218.7
  Top Layer w4: R54.2@1706.96,1200 1712.96,1206 1843.08,1206 1844.58,1204.5 1845.5,1204.5 J3.7@1900,1150
NetJ3_8: J3.8 R53.2 | length 93
  Top Layer w4: R53.2@1706.96,1150 J3.8@1800,1150
NetJ3_9: J3.9 R58.2 | length 213.8
  Top Layer w4: R58.2@1706.96,1100 1850,1100 J3.9@1900,1050
NetJ3_10: J3.10 R57.2 | length 93
  Top Layer w4: R57.2@1706.96,1050 J3.10@1800,1050
NetJ3_11: J3.11 R60.2 | length 213.8
  Top Layer w4: R60.2@1706.96,1000 1850,1000 J3.11@1900,950
NetJ3_12: J3.12 R59.2 | length 93
  Top Layer w4: R59.2@1706.96,950 J3.12@1800,950
NetJ3_13: J3.13 R62.2 | length 213.8
  Top Layer w4: R62.2@1706.96,900 1850,900 J3.13@1900,850
NetJ3_14: J3.14 R61.2 | length 93
  Top Layer w4: R61.2@1706.96,850 J3.14@1800,850
NetJ3_15: J3.15 R64.2 | length 213.8
  Top Layer w4: R64.2@1706.96,800 1850,800 J3.15@1900,750
NetJ3_16: J3.16 R63.2 | length 93
  Top Layer w4: R63.2@1706.96,750 J3.16@1800,750
NetJ3_17: J3.17 R66.1 | length 213.8
  Top Layer w5.8: R66.1@1706.96,700 1850,700 J3.17@1900,650
NetJ3_18: J3.18 R65.2 | length 93
  Top Layer w5.8: R65.2@1706.96,650 J3.18@1800,650
NetJ3_19: J3.19 R68.1 | length 213.8
  Top Layer w4: R68.1@1706.96,600 1850,600 J3.19@1900,550
NetJ3_20: J3.20 R67.1 | length 93
  Top Layer w4: R67.1@1706.96,550 J3.20@1800,550
NetQ1_1: Q1.1 Q1.2 Q1.3 R1.2 R3.2 R6.2 | length 193.5
  Bottom Layer w4: R3.2@779.96,562.5 779.96,593.96 794,608 R1.2@840,608 885,608 900.04,592.96 R6.2@900.04,563
NetQ1_5: Q1.5 Q1.6 Q1.7 Q1.8 Q2.5 Q2.6 Q2.7 Q2.8
NetQ3_3: Q3.3 R72.1 | length 47.1
  Top Layer w10: R72.1@490,123.62 v1@513.62,123.62
  Bottom Layer w10: Q3.3@514,100.5 v1(514,124)
NetQ4_3: Q4.3 R73.1 | length 46.1
  Top Layer w10: v1(586,124) R73.1@609.62,124
  Bottom Layer w10: Q4.3@586,101.5 v1(586,124)
NetQ5_3: Q5.3 R74.1 | length 47.1
  Top Layer w10: R74.1@490,323.62 v1@513.62,323.62
  Bottom Layer w10: Q5.3@514,300.5 v1(514,324)
NetQ6_3: Q6.3 R86.1 | length 47.1
  Top Layer w10: v1(586,324) R86.1@609.62,324
  Bottom Layer w10: Q6.3@586,300.5 v1(586,324)
NetQ7_3: Q7.3 R87.1 | length 47.1
  Top Layer w10: v1(1486,124) R87.1@1509.62,124
  Bottom Layer w10: Q7.3@1486,100.5 v1(1486,124)
NetQ8_3: Q8.3 R89.1 | length 47.1
  Top Layer w10: R89.1@1390,123.62 v1@1413.62,123.62
  Bottom Layer w10: Q8.3@1414,100.5 v1(1414,124)
NetQ9_3: Q9.3 R90.1 | length 47.1
  Top Layer w10: R90.1@1390.38,324 v1(1414,324)
  Bottom Layer w10: Q9.3@1414,300.5 v1(1414,324)
NetQ10_3: Q10.3 R96.1 | length 47.1
  Top Layer w10: v1(1486,324) R96.1@1509.62,324
  Bottom Layer w10: Q10.3@1486,300.5 v1(1486,324)
NetR8_2: R8.2 U1.7 | length 90.1
  Bottom Layer w8: R8.2@1283,901.38 1320.62,939 U1.7@1357.51,939
NetR9_1: R9.1 U1.3 | length 136.5
  Bottom Layer w4: U1.3@1546.49,889 1548.99,886.5 R9.1@1682,886.5
NetR12_1: R12.1 S1.8 | length 147.3
  Top Layer w10: v1(580,1923) 692,1923 S1.8@700,1931
  Bottom Layer w10: R12.1@579.96,1899 v1(580,1923)
NetR13_1: R13.1 S1.7 | length 136
  Top Layer w10: v1(580,1873) S1.7@692,1873
  Bottom Layer w10: R13.1@579.96,1849 v1(580,1873)
NetR14_1: R14.1 S1.6 | length 134
  Top Layer w10: v1(581,1823) S1.6@692,1823
  Bottom Layer w10: R14.1@581,1800.04 v1(581,1823)
NetR15_1: R15.1 S1.5 | length 134
  Top Layer w10: v1(581,1773) S1.5@692,1773
  Bottom Layer w10: R15.1@581,1750.04 v1(581,1773)
NetR27_1: R27.1 S3.2 | length 39.1
  Top Layer w12: S3.2@1557.93,1524 R27.1@1597.04,1524
NetR28_2: R28.2 U2.G2 | length 190.5
  Top Layer w4: v1(802,914.37) 803,915.37 837.8,915.37 842.77,920.34 911.91,920.34 U2.G2@921.26,929.69
  Bottom Layer w4: v1(802,914.37) 840,914.37 R28.2@859,895.37
NetR42_1: R42.1 S2.8 | length 87.9
  Top Layer w10: S2.8@1600,1931 1609,1931 v1(1640,1900)
  Bottom Layer w10: R42.1@1604.96,1900 v1(1640,1900)
NetR43_1: R43.1 S2.7 | length 87.9
  Top Layer w10: S2.7@1600,1881 1609,1881 v1(1640,1850)
  Bottom Layer w10: R43.1@1604.96,1850 v1(1640,1850)
NetR44_1: R44.1 S2.6 | length 87.9
  Top Layer w10: S2.6@1600,1831 1609,1831 v1(1640,1800)
  Bottom Layer w10: R44.1@1604.96,1800 v1(1640,1800)
NetR45_1: R45.1 S2.5 | length 87.9
  Top Layer w10: S2.5@1600,1781 1609,1781 v1(1640,1750)
  Bottom Layer w10: R45.1@1604.96,1750 v1(1640,1750)
NetR56_2: R56.2 U2.F1 | length 206.1
  Top Layer w4: v1(802,949.37) 834,949.37 841.19,942.18 889.81,942.18 897,949.37 U2.F1@901.57,949.37
  Bottom Layer w4: v1(802,949.37) 880.89,949.37 885.04,953.52 R56.2@885.04,969.37
NetR81_1: R81.1 R83.2 U5.8 | length 519.6
  Bottom Layer w10: R81.1@325,687.38 325,634.62 R83.2@324,633.62 286,595.62 286,551 333,504 473,504 492,523 492,607.5 506,621.5 U5.8@506,650.88
NetR91_1: R91.1 R93.2 U6.8 | length 467.6
  Bottom Layer w10: R91.1@1219.6,1321.38 1219.6,1276.62 1194,1251.02 1194,1198.96 1225.6,1167.36 1338.36,1167.36 1380,1209 1445,1209 1467.6,1231.6 U6.8@1467.6,1252.88
NetR101_1: R101.1 R103.2 U7.8 | length 529.4
  Bottom Layer w10: U7.8@472,1472.69 445.12,1472.69 423.12,1494.69 340.12,1494.69 318.12,1516.69 318.12,1662.69 350.12,1694.69 434.12,1694.69 439.74,1689.06 R103.2@439.74,1663.69 R101.1@488.5,1663.69
RESETZ: R54.1 U2.F11 | length 723.2
  Top Layer w4: U2.F11@1098.43,949.37 1234.99,949.37 1524.62,1239 1638,1239 R54.1@1683,1194
RPD_G1: R10.1 R22.1 U2.K9 | length 128.6
  Top Layer w4: U2.K9@1059.06,870.63 1049,860.57 1049,841.72 1075.05,815.67 R22.1@1075.05,789 ; R22.1@1078,788.96 R10.1@1110.05,789 R10.1@1110.05,789
RPD_G2: R11.1 R30.1 U2.K10 | length 206.2
  Top Layer w4: U2.K10@1078.74,870.63 1087.7,861.67 1152.33,861.67 1206,808 R11.1@1206,789 ; R11.1@1206.96,789 R11.1@1206,789 ; R30.1@1239,788.96 1206.04,788.96 R11.1@1206,789
SENSEN: R2.1 R3.1 U2.A10 | length 855.1
  Top Layer w4: U2.A10@1078.74,1047.8 1078.74,1064.74 1097,1083 1097,1098 1113,1114 v1(1130,1114)
  MidLayer2 w4: v1(751,584) 980,813 980,990 1104,1114 v1(1130,1114)
  Bottom Layer w4: R2.1@750.04,527.5 R3.1@750.04,562.5 v1@750.04,583.04
SENSEP: R5.1 R6.1 U2.B10 | length 802
  Top Layer w4: U2.B10@1078.74,1028.11 1080.11,1028.11 1088,1036 1088,1061 1115,1088 v1(1115,1095)
  MidLayer2 w4: v1(956,581) 995,581 1173,759 1173,1037 v1(1115,1095)
  Bottom Layer w4: R5.1@929.96,528 R6.1@929.96,563 947.96,581 v1(956,581)
SPI_CLK: R38.2 U1.6 U2.A3 | length 1998.9
  Top Layer w4: R38.2@322.96,900 576,900 762,1086 762,1132 952,1322 v1(992,1322) 992,1308 940.94,1256.94 U2.A3@940.94,1047.8
  MidLayer1 w4: v1(992,1322) 1204,1322 1279,1247 1279,948 1312,915 v1(1423,915)
  Bottom Layer w4: 1376,901 1376,910 1381,915 v1(1423,915)
SPI_CSZ: R4.2 R66.2 U1.1 U2.B3 | length 1741.9
  Top Layer w4: U2.B3@940.94,1028.11 931,1038.06 931,1279 v1(959,1307)
  Top Layer w12: v1@1655.5,699.9 1676.94,699.9 R66.2@1677.04,700
  MidLayer1 w4: v1(959,1307) 959,1317 981,1339 1232,1339 1324,1247 1324,1032 1367,989 v1(1482,989) 1481,990 1639,990 1669,960 1669,718.6 v1(1650.3,699.9)
  Bottom Layer w4: v1(1482,989) U1.1@1546.49,989 1621.62,989 R4.2@1624,991.38
SPI_MISO: R7.2 R62.1 U1.2 U2.A4 | length 1557
  Top Layer w4: U2.A4@960.63,1047.8 960.63,1210.63 v1(994,1244) ; v1(1482,939) 1521,900 R62.1@1677.04,900
  MidLayer1 w4: v1(994,1244) 1024,1274 1151.1,1274 1207,1218.1 1207,896 1252.29,850.71 1456.71,850.71 1482,876 v1(1482,939)
  Bottom Layer w4: v1(1482,939) U1.2@1546.49,939 1550.49,935 1672,935 R7.2@1676.38,939.38
SPI_MOSI: R60.1 U1.5 U2.B4 | length 1487.4
  Top Layer w4: U2.B4@960.63,1028.11 951,1037.74 951,1234 v1(976,1259) ; v1@1423,887 1444,887 1461,904 1461,946 1481,966 1570,966 1604,1000 R60.1@1677.04,1000
  MidLayer1 w4: v1(976,1259) 1018,1301 1178,1301 1242,1237 1242,913 1271,884 v1(1423,884)
  Bottom Layer w4: U1.5@1365.51,847 1415,847 1423,855 v1(1423,884)
SWD_CLK: R24.1 R41.1 U2.G4 | length 978.5
  Top Layer w4: v1(254,566) 306.96,566 R41.1@322.96,550 R24.1@363.04,550 ; v1@945,929 v1(947,929) 959.94,929 U2.G4@960.63,929.69
  MidLayer1 w4: v1(254,566) 254,572 517,835 809.91,835 903.91,929 v1(947,929)
SWD_DATA: R20.1 R39.1 U2.F4 | length 940
  Top Layer w4: v1(253.33,667) 305.96,667 R39.1@322.96,650 R20.1@362.04,650 ; v1(938,948) 959.26,948 U2.F4@960.63,949.37
  MidLayer1 w4: v1(253.33,667) 325,667 503,845 773,845 795,867 823.72,867 904.72,948 v1(938,948)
